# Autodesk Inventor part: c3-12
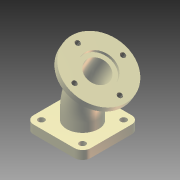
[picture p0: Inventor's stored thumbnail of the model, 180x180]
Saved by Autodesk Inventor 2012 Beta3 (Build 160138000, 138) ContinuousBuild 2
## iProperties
Created: 2010-11
Part Number: c3-12
Material: Cast Iron
Document SubType Name: Modeling
Designer: Beta-8540w
Density: 7.25 g/cm^3
Mass: 1087.5 g
Surface Area: 260 cm^2
Volume: 150 cm^3
Author: Beta-8540w
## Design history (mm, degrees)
sketch "Sketch1"
  geometry: L1 (-50, -50)-(50, -50); L2 (50, -50)-(50, 50); L3 (50, 50)-(-50, 50); L4 (-50, 50)-(-50, -50); C1 r 20 at (0, 0); C2 r 28 at (0, 0); 3 further points
  constraints: 8 end point, 3 perpendicular, 2 centre point, 2 coincident, 2 midpoint, 1 horizontal, 1 horizontal alignment, 1 parallel, 1 vertical alignment
  dimensions: "Width" = 100 distance of L1.start L1.end; "d6" = 40 diameter of C1; "d7" = 8 radial gap between concentric circles of C2 C1
extrude "Extrusion1" new body sketch "Sketch1" distance "d3" = 15; taper "d4" = 0 deg
fillet "Fillet1" dims "d5" = 14
sketch "Sketch2"
  geometry: L1 (0, 0)-(0, 30); L2 (-13.397, 80)-(-28.397, 105.981); A1 r 100 centre (-100, 30) between (0, 30) and (-13.397, 80)
  constraints: 4 end point, 2 point on circle, 2 tangent, 1 centre point, 1 vertical
  dimensions: "d8" = 30 distance of L1.start L1.end; "d9" = 100 radius of A1; "d10" = 30 distance of L2.start L2.end; "d11" = 30 deg angle of L2 L1
sketch "Sketch3"
  geometry: L1 (-13.397, 80)-(-28.397, 105.981) reference; L2 (-28.397, 105.981)-(-76.029, 78.481); L3 (-76.029, 78.481)-(-71.029, 69.821); L4 (-71.029, 69.821)-(-23.397, 97.321); L5 (-23.397, 97.321)-(-28.397, 105.981); 1 further point
  constraints: 8 end point, 2 parallel, 2 perpendicular
  dimensions: "d16" = 10 distance of L3.end L2.end; "d17" = 110 diameter of L3 L5
revolve "Revolution1" sketch "Sketch3" stored, may be unused: angle "d18" = 90 deg
sweep "Sweep1" dims "d19" = 0
sweep "Sweep2" dims "d20" = 0
sketch "Sketch4"
  geometry: C1 r 20 at (0, 0) reference; C2 r 55 at (0, 0) reference; C3 r 27.5 at (0, 0); 1 further point
  constraints: 1 centre point, 1 coincident
  dimensions: "d21" = 55 diameter of C3
extrude "Extrusion2" cut sketch "Sketch4" distance "d22" = 5; taper "d23" = 0 deg
sketch "Sketch5"
  geometry: L1 (0, 0)-(0, 9.711); L2 (-25, 0)-(-27, 0); L3 (-27, 0)-(-27, 1.5); L4 (-26.5, 2)-(-25.5, 2); L5 (-25, 1.5)-(-25, 0); A1 r 0.5 centre (-25.5, 1.5) between (-25, 1.5) and (-25.5, 2); A2 r 0.5 centre (-26.5, 1.5) between (-26.5, 2) and (-27, 1.5); 1 further point
  constraints: 10 end point, 4 point on circle, 4 tangent, 3 point on line, 2 centre point, 2 parallel, 1 equal radius, 1 horizontal, 1 perpendicular, 1 vertical
  dimensions: "d24" = 2 distance of L2.start L2.end; "d25" = 2 distance of point (-25, 2) L2.start; "d26" = 50 diameter of L5 L1; "d27" = 0.5 radius of A1
revolve "Revolution2" sketch "Sketch5" stored, may be unused: angle "d28" = 90 deg
hole "Hole1" diameter "d31" = 11; stored, may be unused: countersink angle "d35" = 7.5 deg, drill point angle "d37" = 118 deg; dims "d29" = 10, "d30" = 10, "d32" = 6, "d33" = 28, "d34" = 2, "d36" = 8
pattern_circular "Circular Pattern1" dims angle "d39" = 360 deg
sketch "Hole Sketch" dims "d41" = 85
  geometry: L1 (0, -42.5)-(-42.5, 0); L2 (-42.5, 0)-(0, 42.5); L3 (0, 42.5)-(42.5, 0); L4 (42.5, 0)-(0, -42.5); C1 r 27.5 at (0, 0) reference; 2 further points
  constraints: 8 end point, 2 coincident, 2 horizontal alignment, 11 other
hole "Hole2" sketch "Hole Sketch" at (0, -42.5), (-42.5, 0), (0, 42.5), (42.5, 0) diameter "d42" = 8.376; stored, may be unused: countersink angle "d46" = 90 deg, drill point angle "d48" = 118 deg; dims "d43" = 6, "d44" = 4, "d45" = 2, "d47" = 8
body "Solid1"
